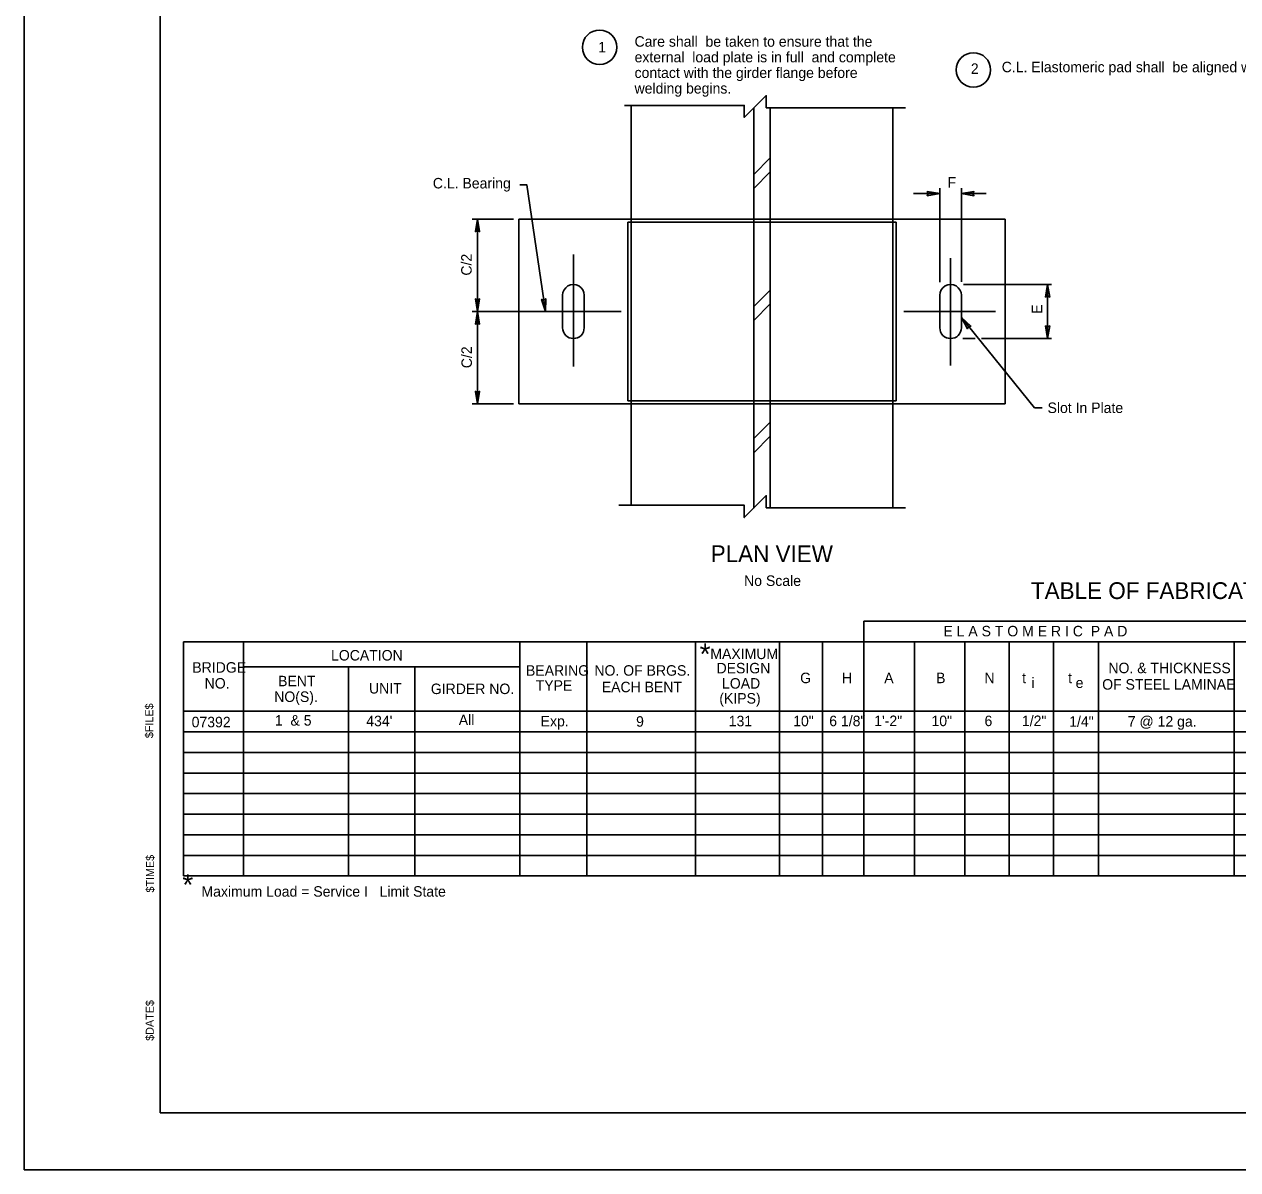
# Model space of a CAD drawing. Extents: x -193 to 149, y 507 to 725.
# Drawn here: x -192.5 to -47.9, y 507.1 to 643.6 of the extents above; entities that cross this region are included whole.
import ezdxf

# ---------------------------------------------------------------- set-up
doc = ezdxf.new("R2010")
doc.units = 0
for name, color, linetype in [('border', 7, 'Continuous'), ('Border 2660-Hwy18 - Level 62', 7, 'Continuous'), ('Level 20', 7, 'Continuous'), ('Level 31', 7, 'Continuous'), ('Level 40', 7, 'Continuous'), ('Level 41', 7, 'Continuous'), ('Level 42', 7, 'Continuous'), ('Level 43', 7, 'Continuous')]:
    doc.layers.add(name, color=color, linetype=linetype)

msp = doc.modelspace()

# ---------------------------------------------------------------- linework, layer by layer
at = {"layer": 'border'}
for p, q in [((-176.33, 513.86), (-176.33, 719.31)), ((143.78, 513.86), (-176.33, 513.86))]:
    msp.add_line(p, q, dxfattribs=at)
at = {"layer": 'Border 2660-Hwy18 - Level 62'}
msp.add_lwpolyline([(-192.53, 725.17), (148.65, 725.17), (148.65, 507.07), (-192.53, 507.07)], close=True, dxfattribs=at)
at = {"layer": 'Level 20'}
for p, q in [((-127.1, 602.8), (-127.1, 616.17)), ((-82.15, 602.94), (-82.15, 615.72)), ((-139.16, 609.37), (-121.39, 609.37)), ((-87.71, 609.37), (-76.8, 609.37))]:
    msp.add_line(p, q, dxfattribs=at)
at = {"layer": 'Level 31'}
for p, q in [((-120.21, 586.27), (-120.21, 633.94)), ((-105.61, 633.62), (-105.61, 585.93)), ((-103.64, 633.66), (-103.64, 585.98)), ((-89.04, 585.98), (-89.04, 633.66)), ((-133.6, 598.35), (-133.6, 620.39)), ((-133.6, 620.39), (-120.21, 620.39)), ((-120.21, 620.39), (-89.04, 620.39)), ((-89.04, 620.39), (-75.66, 620.39)), ((-75.66, 598.35), (-75.66, 620.39)), ((-120.61, 598.74), (-120.61, 620)), ((-120.61, 620), (-88.65, 620)), ((-88.65, 598.74), (-88.65, 620)), ((-128.39, 611.3), (-128.39, 607.44)), ((-125.82, 611.3), (-125.82, 607.44)), ((-83.44, 611.3), (-83.44, 607.44)), ((-80.87, 611.3), (-80.87, 607.44)), ((-120.61, 598.74), (-88.65, 598.74)), ((-133.6, 598.35), (-120.21, 598.35)), ((-120.21, 598.35), (-89.04, 598.35)), ((-89.04, 598.35), (-75.66, 598.35))]:
    msp.add_line(p, q, dxfattribs=at)
for centre, start, end in [((-127.1, 611.3), 0, 180.0422), ((-82.15, 611.3), 0, 180.0422), ((-127.1, 607.44), 180.0422, 0), ((-82.15, 607.44), 180.0422, 0)]:
    msp.add_arc(centre, 1.29, start, end, dxfattribs=at)
at = {"layer": 'Level 40'}
for p, q in [((-166.4, 570.01), (-166.4, 542.09)), ((-133.5, 570.01), (-133.5, 542.09)), ((-125.49, 570.01), (-125.49, 542.09)), ((-112.53, 570.01), (-112.53, 542.09)), ((-102.55, 570.01), (-102.55, 542.09)), ((-97.43, 570.01), (-97.43, 542.09)), ((-86.47, 570.01), (-86.47, 542.09)), ((-80.45, 570.01), (-80.45, 542.09)), ((-75.17, 570.01), (-75.17, 542.09)), ((-69.89, 570.01), (-69.89, 542.09)), ((-64.51, 570.01), (-64.51, 542.09)), ((-48.37, 570.01), (-48.37, 542.09)), ((-166.4, 567.03), (-133.5, 567.03)), ((-153.9, 567.03), (-153.9, 542.09)), ((-146, 567.03), (-146, 542.09)), ((-102.55, 567.56), (-102.55, 547)), ((-173.56, 561.72), (58.08, 561.72)), ((-173.56, 559.27), (58.08, 559.27)), ((-173.56, 556.81), (58.08, 556.81)), ((-173.56, 556.81), (58.08, 556.81)), ((-173.56, 554.36), (58.08, 554.36)), ((-173.56, 554.36), (58.08, 554.36)), ((-173.56, 551.91), (58.08, 551.91)), ((-173.56, 551.91), (58.08, 551.91)), ((-173.56, 549.45), (58.08, 549.45)), ((-173.56, 547), (58.08, 547)), ((-173.56, 544.54), (58.08, 544.54))]:
    msp.add_line(p, q, dxfattribs=at)
for centre in [(-123.98, 640.87), (-79.43, 638.17)]:
    msp.add_circle(centre, 2.05, dxfattribs=at)
at = {"layer": 'Level 41'}
for p, q in [((-92.48, 572.46), (58.08, 572.46)), ((-92.48, 572.46), (-92.48, 542.09)), ((-173.56, 570.01), (58.08, 570.01)), ((-173.56, 570.01), (-173.56, 542.09)), ((-173.56, 542.09), (58.08, 542.09))]:
    msp.add_line(p, q, dxfattribs=at)
at = {"layer": 'Level 42'}
for p, q in [((-105.61, 625.71), (-103.64, 627.67)), ((-105.61, 624.03), (-103.64, 626.02)), ((-105.61, 609.96), (-103.64, 611.93)), ((-105.61, 608.28), (-103.64, 610.28)), ((-105.61, 594.22), (-103.64, 596.19)), ((-105.61, 592.54), (-103.64, 594.53))]:
    msp.add_line(p, q, dxfattribs=at)
at = {"layer": 'Level 43'}
for p, q in [((-86.59, 623.42), (-83.44, 623.42)), ((-83.44, 612.86), (-83.44, 624.07)), ((-80.87, 612.91), (-80.87, 624.07)), ((-77.9, 623.42), (-80.87, 623.42)), ((-134.24, 620.39), (-139.16, 620.39)), ((-138.52, 609.37), (-138.52, 620.39)), ((-80.62, 612.59), (-70.14, 612.59)), ((-70.59, 612.59), (-70.59, 606.16)), ((-138.52, 598.35), (-138.52, 609.37)), ((-80.71, 606.16), (-79.23, 606.16)), ((-78.47, 606.16), (-70.14, 606.16)), ((-134.24, 598.35), (-139.16, 598.35))]:
    msp.add_line(p, q, dxfattribs=at)
for points in [[(-121, 633.94), (-106.74, 633.94), (-106.74, 632.5), (-104.11, 635.11), (-104.11, 633.66), (-87.51, 633.66)], [(-133.48, 624.45), (-132.64, 624.45), (-130.42, 609.37)], [(-80.87, 608.64), (-72.15, 597.88), (-71.24, 597.88)], [(-121.67, 586.27), (-106.74, 586.27), (-106.74, 584.81), (-104.11, 587.42), (-104.11, 585.98), (-87.51, 585.98)]]:
    msp.add_lwpolyline(points, dxfattribs=at)
for points in [[(-83.44, 623.42), (-84.94, 623.67), (-84.81, 623.42), (-84.94, 623.17)], [(-80.87, 623.42), (-79.37, 623.17), (-79.5, 623.42), (-79.37, 623.67)], [(-138.52, 620.39), (-138.77, 618.89), (-138.52, 619.02), (-138.27, 618.89)], [(-70.59, 612.59), (-70.84, 611.09), (-70.59, 611.22), (-70.34, 611.09)], [(-138.52, 609.37), (-138.27, 610.87), (-138.52, 610.74), (-138.77, 610.87)], [(-130.42, 609.37), (-130.39, 610.89), (-130.62, 610.73), (-130.89, 610.82)], [(-138.52, 609.37), (-138.77, 607.87), (-138.52, 608), (-138.27, 607.87)], [(-80.87, 608.64), (-80.12, 607.31), (-80, 607.57), (-79.73, 607.63)], [(-70.59, 606.16), (-70.34, 607.66), (-70.59, 607.53), (-70.84, 607.66)], [(-138.52, 598.35), (-138.27, 599.85), (-138.52, 599.72), (-138.77, 599.85)]]:
    msp.add_lwpolyline(points, close=True, dxfattribs=at)

# ---------------------------------------------------------------- texts
at = {"layer": 'border'}
for s, p in [('$FILE$', (-177.16, 558.52)), ('$TIME$', (-177.06, 540.11)), ('$DATE$', (-177.1, 522.44))]:
    msp.add_text(s, height=0.96, rotation=89.9999, dxfattribs=at).set_placement(p)
at = {"layer": 'Level 40'}
for s, height, p in [('Care shall  be taken to ensure that the', 1.25, (-119.81, 640.93)), ('1', 1.25, (-124.14, 640.26)), ('external  load plate is in full  and complete', 1.25, (-119.81, 639.07)), ('C.L. Elastomeric pad shall  be aligned with C.L. Girder.', 1.25, (-76.06, 637.89)), ('contact with the girder flange before', 1.25, (-119.81, 637.21)), ('2', 1.25, (-79.74, 637.69)), ('welding begins.', 1.25, (-119.81, 635.35)), ('C.L. Bearing', 1.25, (-143.85, 624.04)), ('F', 1.25, (-82.51, 624.14)), ('Slot In Plate', 1.25, (-70.6, 597.27)), ('No Scale', 1.25, (-106.76, 576.66)), ('E L A S T O M E R I C  P A D', 1.25, (-83.01, 570.65)), ('*', 2.5, (-112.06, 567.3)), ('LOCATION', 1.25, (-155.98, 567.77)), ('MAXIMUM', 1.25, (-110.78, 567.94)), ('BRIDGE', 1.25, (-172.51, 566.32)), ('BEARING', 1.25, (-132.75, 565.96)), ('NO. OF BRGS.', 1.25, (-124.6, 565.96)), ('DESIGN', 1.25, (-110.04, 566.24)), ('NO. & THICKNESS', 1.25, (-63.35, 566.26)), ('NO.', 1.25, (-171.04, 564.43)), ('BENT', 1.25, (-162.29, 564.7)), ('TYPE', 1.25, (-131.59, 564.17)), ('LOAD', 1.25, (-109.39, 564.42)), ('G', 1.25, (-100.08, 565.07)), ('H', 1.25, (-95.11, 565.07)), ('A', 1.25, (-90.06, 565.07)), ('B', 1.25, (-83.88, 565.07)), ('N', 1.25, (-78.12, 565.07)), ('t ', 1.25, (-73.63, 565.07)), ('i', 1.25, (-72.52, 564.49)), ('t ', 1.25, (-68.15, 565.07)), ('e', 1.25, (-67.25, 564.49)), ('OF STEEL LAMINAE', 1.25, (-64.09, 564.3)), ('NO(S).', 1.25, (-162.75, 562.83)), ('UNIT', 1.25, (-151.45, 563.83)), ('GIRDER NO.', 1.25, (-144.09, 563.77)), ('EACH BENT', 1.25, (-123.72, 563.99)), ('(KIPS)', 1.25, (-109.71, 562.64)), ('07392', 1.25, (-172.59, 559.81)), ('1  & 5', 1.25, (-162.67, 560.01)), ("434'", 1.25, (-151.78, 559.94)), ('All', 1.25, (-140.76, 560.07)), ('Exp.', 1.25, (-131, 559.92)), ('9', 1.25, (-119.63, 559.88)), ('131', 1.25, (-108.59, 559.93)), ('10"', 1.25, (-100.91, 559.94)), ('6 1/8"', 1.25, (-96.61, 559.94)), ('1\'-2"', 1.25, (-91.25, 559.96)), ('10"', 1.25, (-84.43, 559.95)), ('6', 1.25, (-78.11, 559.95)), ('1/2"', 1.25, (-73.65, 559.96)), ('1/4"', 1.25, (-68.02, 559.88)), ('7 @ 12 ga.', 1.25, (-61.04, 559.89)), ('*', 2.5, (-173.69, 539.79)), ('Maximum Load = Service I   Limit State', 1.25, (-171.42, 539.62))]:
    msp.add_text(s, height=height, dxfattribs=at).set_placement(p)
for s, p in [('C/2', (-139.22, 613.65)), ('E', (-71.24, 609.09)), ('C/2', (-139.19, 602.61))]:
    msp.add_text(s, height=1.25, rotation=90, dxfattribs=at).set_placement(p)
at = {"layer": 'Level 41'}
for s, p in [(' PLAN VIEW ', (-111.48, 579.5)), (' TABLE OF FABRICATOR VARIABLES ', (-73.32, 575.1))]:
    msp.add_text(s, height=2, dxfattribs=at).set_placement(p)

doc.saveas('drawing.dxf')
